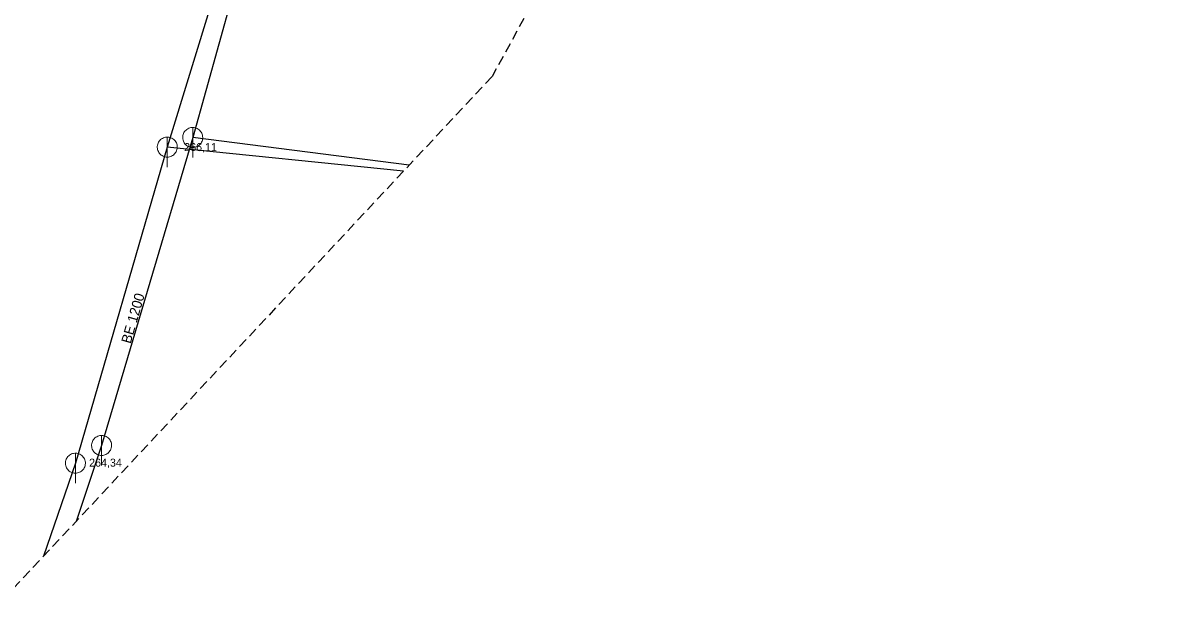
# Model space of a CAD drawing. Extents: x -725153 to -724843, y -978146 to -977794.
# Drawn here: x -724958 to -724842.7, y -978146.1 to -978087.1 of the extents above; entities that cross this region are included whole.
import ezdxf

# ---------------------------------------------------------------- set-up
doc = ezdxf.new("R2010")
doc.units = 0
doc.header["$LTSCALE"] = 0.32
doc.linetypes.add('MEDIUM_DASHED', pattern=[4.5, 3, -1.5])
doc.layers.add('1', color=7, linetype='Continuous')
for name, color, linetype, lineweight in [('14', 7, 'Continuous', 25), ('22', 7, 'Continuous', 13), ('63', 7, 'MEDIUM_DASHED', 25)]:
    doc.layers.add(name, color=color, linetype=linetype, lineweight=lineweight)

msp = doc.modelspace()

# ---------------------------------------------------------------- linework, layer by layer
at = {"layer": '14'}
for p, q in [((-724927.944, -978048.326), (-724943.585, -978099.465)), ((-724927.274, -978049.14), (-724941.044, -978098.504)), ((-724943.585, -978099.465), (-724952.772, -978131.071)), ((-724941.044, -978098.504), (-724950.152, -978129.296)), ((-724919.95, -978101.862), (-724943.585, -978099.465)), ((-724919.391, -978101.264), (-724941.044, -978098.504)), ((-724950.152, -978129.296), (-724952.698, -978136.885)), ((-724952.772, -978131.071), (-724955.962, -978140.375))]:
    msp.add_line(p, q, dxfattribs=at)
at = {"layer": '22'}
for p, q in [((-724941.044, -978100.504), (-724941.043, -978097.504)), ((-724943.585, -978101.465), (-724943.584, -978098.465)), ((-724950.152, -978131.296), (-724950.151, -978128.296)), ((-724952.772, -978133.07), (-724952.771, -978130.07))]:
    msp.add_line(p, q, dxfattribs=at)
for points in [[(-724940.044, -978098.504), (-724940.049, -978098.395), (-724940.067, -978098.287), (-724940.097, -978098.181), (-724940.137, -978098.08), (-724940.189, -978097.983), (-724940.251, -978097.893), (-724940.323, -978097.81), (-724940.403, -978097.736), (-724940.491, -978097.67), (-724940.585, -978097.615), (-724940.685, -978097.57), (-724940.79, -978097.537), (-724940.897, -978097.515), (-724941.006, -978097.505), (-724941.116, -978097.507), (-724941.224, -978097.521), (-724941.331, -978097.546), (-724941.434, -978097.583), (-724941.532, -978097.632), (-724941.624, -978097.69), (-724941.71, -978097.759), (-724941.787, -978097.836), (-724941.856, -978097.922), (-724941.915, -978098.014), (-724941.963, -978098.112), (-724942, -978098.215), (-724942.026, -978098.322), (-724942.04, -978098.43), (-724942.043, -978098.54), (-724942.033, -978098.649), (-724942.012, -978098.756), (-724941.978, -978098.86), (-724941.934, -978098.96), (-724941.879, -978099.055), (-724941.813, -978099.143), (-724941.739, -978099.223), (-724941.656, -978099.295), (-724941.566, -978099.357), (-724941.47, -978099.409), (-724941.368, -978099.45), (-724941.263, -978099.48), (-724941.155, -978099.498), (-724941.045, -978099.504), (-724940.936, -978099.498), (-724940.828, -978099.48), (-724940.723, -978099.451), (-724940.621, -978099.41), (-724940.524, -978099.358), (-724940.434, -978099.296), (-724940.351, -978099.225), (-724940.276, -978099.145), (-724940.211, -978099.057), (-724940.155, -978098.963), (-724940.111, -978098.863), (-724940.077, -978098.759), (-724940.055, -978098.651), (-724940.045, -978098.542)], [(-724942.585, -978099.465), (-724942.59, -978099.356), (-724942.608, -978099.248), (-724942.638, -978099.142), (-724942.678, -978099.041), (-724942.73, -978098.944), (-724942.792, -978098.854), (-724942.864, -978098.771), (-724942.944, -978098.697), (-724943.032, -978098.631), (-724943.126, -978098.576), (-724943.226, -978098.531), (-724943.331, -978098.498), (-724943.438, -978098.476), (-724943.547, -978098.466), (-724943.657, -978098.468), (-724943.765, -978098.482), (-724943.872, -978098.507), (-724943.975, -978098.544), (-724944.073, -978098.593), (-724944.165, -978098.651), (-724944.251, -978098.72), (-724944.328, -978098.797), (-724944.397, -978098.883), (-724944.456, -978098.975), (-724944.504, -978099.073), (-724944.541, -978099.176), (-724944.567, -978099.283), (-724944.581, -978099.391), (-724944.584, -978099.501), (-724944.574, -978099.61), (-724944.553, -978099.717), (-724944.519, -978099.821), (-724944.475, -978099.921), (-724944.42, -978100.016), (-724944.354, -978100.104), (-724944.28, -978100.184), (-724944.197, -978100.256), (-724944.107, -978100.318), (-724944.011, -978100.37), (-724943.909, -978100.411), (-724943.804, -978100.441), (-724943.696, -978100.459), (-724943.586, -978100.465), (-724943.477, -978100.459), (-724943.369, -978100.441), (-724943.264, -978100.412), (-724943.162, -978100.371), (-724943.065, -978100.319), (-724942.975, -978100.257), (-724942.892, -978100.186), (-724942.817, -978100.106), (-724942.752, -978100.018), (-724942.696, -978099.924), (-724942.652, -978099.824), (-724942.618, -978099.72), (-724942.596, -978099.612), (-724942.586, -978099.503)], [(-724949.152, -978129.296), (-724949.157, -978129.187), (-724949.175, -978129.079), (-724949.205, -978128.973), (-724949.245, -978128.872), (-724949.297, -978128.775), (-724949.359, -978128.685), (-724949.431, -978128.602), (-724949.511, -978128.528), (-724949.599, -978128.462), (-724949.693, -978128.407), (-724949.793, -978128.362), (-724949.898, -978128.329), (-724950.005, -978128.307), (-724950.114, -978128.297), (-724950.224, -978128.299), (-724950.332, -978128.313), (-724950.439, -978128.338), (-724950.542, -978128.375), (-724950.64, -978128.424), (-724950.732, -978128.482), (-724950.818, -978128.551), (-724950.895, -978128.628), (-724950.964, -978128.714), (-724951.023, -978128.806), (-724951.071, -978128.904), (-724951.108, -978129.007), (-724951.134, -978129.114), (-724951.148, -978129.222), (-724951.151, -978129.332), (-724951.141, -978129.441), (-724951.12, -978129.548), (-724951.086, -978129.652), (-724951.042, -978129.752), (-724950.987, -978129.847), (-724950.921, -978129.935), (-724950.847, -978130.015), (-724950.764, -978130.087), (-724950.674, -978130.149), (-724950.578, -978130.201), (-724950.476, -978130.242), (-724950.371, -978130.272), (-724950.263, -978130.29), (-724950.153, -978130.296), (-724950.044, -978130.29), (-724949.936, -978130.272), (-724949.831, -978130.243), (-724949.729, -978130.202), (-724949.632, -978130.15), (-724949.542, -978130.088), (-724949.459, -978130.017), (-724949.384, -978129.937), (-724949.319, -978129.849), (-724949.263, -978129.755), (-724949.219, -978129.655), (-724949.185, -978129.551), (-724949.163, -978129.443), (-724949.153, -978129.334)], [(-724951.772, -978131.07), (-724951.777, -978130.961), (-724951.795, -978130.853), (-724951.825, -978130.747), (-724951.865, -978130.646), (-724951.917, -978130.549), (-724951.979, -978130.459), (-724952.051, -978130.376), (-724952.131, -978130.302), (-724952.219, -978130.236), (-724952.313, -978130.181), (-724952.413, -978130.136), (-724952.518, -978130.103), (-724952.625, -978130.081), (-724952.734, -978130.071), (-724952.844, -978130.073), (-724952.952, -978130.087), (-724953.059, -978130.112), (-724953.162, -978130.149), (-724953.26, -978130.198), (-724953.352, -978130.256), (-724953.438, -978130.325), (-724953.515, -978130.402), (-724953.584, -978130.488), (-724953.643, -978130.58), (-724953.691, -978130.678), (-724953.728, -978130.781), (-724953.754, -978130.888), (-724953.768, -978130.996), (-724953.771, -978131.106), (-724953.761, -978131.215), (-724953.74, -978131.322), (-724953.706, -978131.426), (-724953.662, -978131.526), (-724953.607, -978131.621), (-724953.541, -978131.709), (-724953.467, -978131.789), (-724953.384, -978131.861), (-724953.294, -978131.923), (-724953.198, -978131.975), (-724953.096, -978132.016), (-724952.991, -978132.046), (-724952.883, -978132.064), (-724952.773, -978132.07), (-724952.664, -978132.064), (-724952.556, -978132.046), (-724952.451, -978132.017), (-724952.349, -978131.976), (-724952.252, -978131.924), (-724952.162, -978131.862), (-724952.079, -978131.791), (-724952.004, -978131.711), (-724951.939, -978131.623), (-724951.883, -978131.529), (-724951.839, -978131.429), (-724951.805, -978131.325), (-724951.783, -978131.217), (-724951.773, -978131.108)]]:
    msp.add_lwpolyline(points, close=True, dxfattribs=at)
at = {"layer": '63'}
msp.add_lwpolyline([(-725126.038, -977904.704), (-725126.038, -977794.451), (-724874.829, -977812.594), (-724855.29, -977827.945), (-724842.73, -977919.358), (-724859.477, -977998.21), (-724911.114, -978092.413), (-724961.356, -978146.144), (-725152.554, -978126.605)], close=True, dxfattribs=at)

# ---------------------------------------------------------------- texts
at = {"layer": '1'}
for s, p in [('266,11', (-724941.894, -978099.864)), ('264,34', (-724951.399, -978131.416))]:
    msp.add_text(s, height=0.8, dxfattribs=at).set_placement(p)
msp.add_text('BE 1200 ', height=1, rotation=74, dxfattribs=at).set_placement((-724947.248, -978119.182))

doc.saveas('drawing.dxf')
